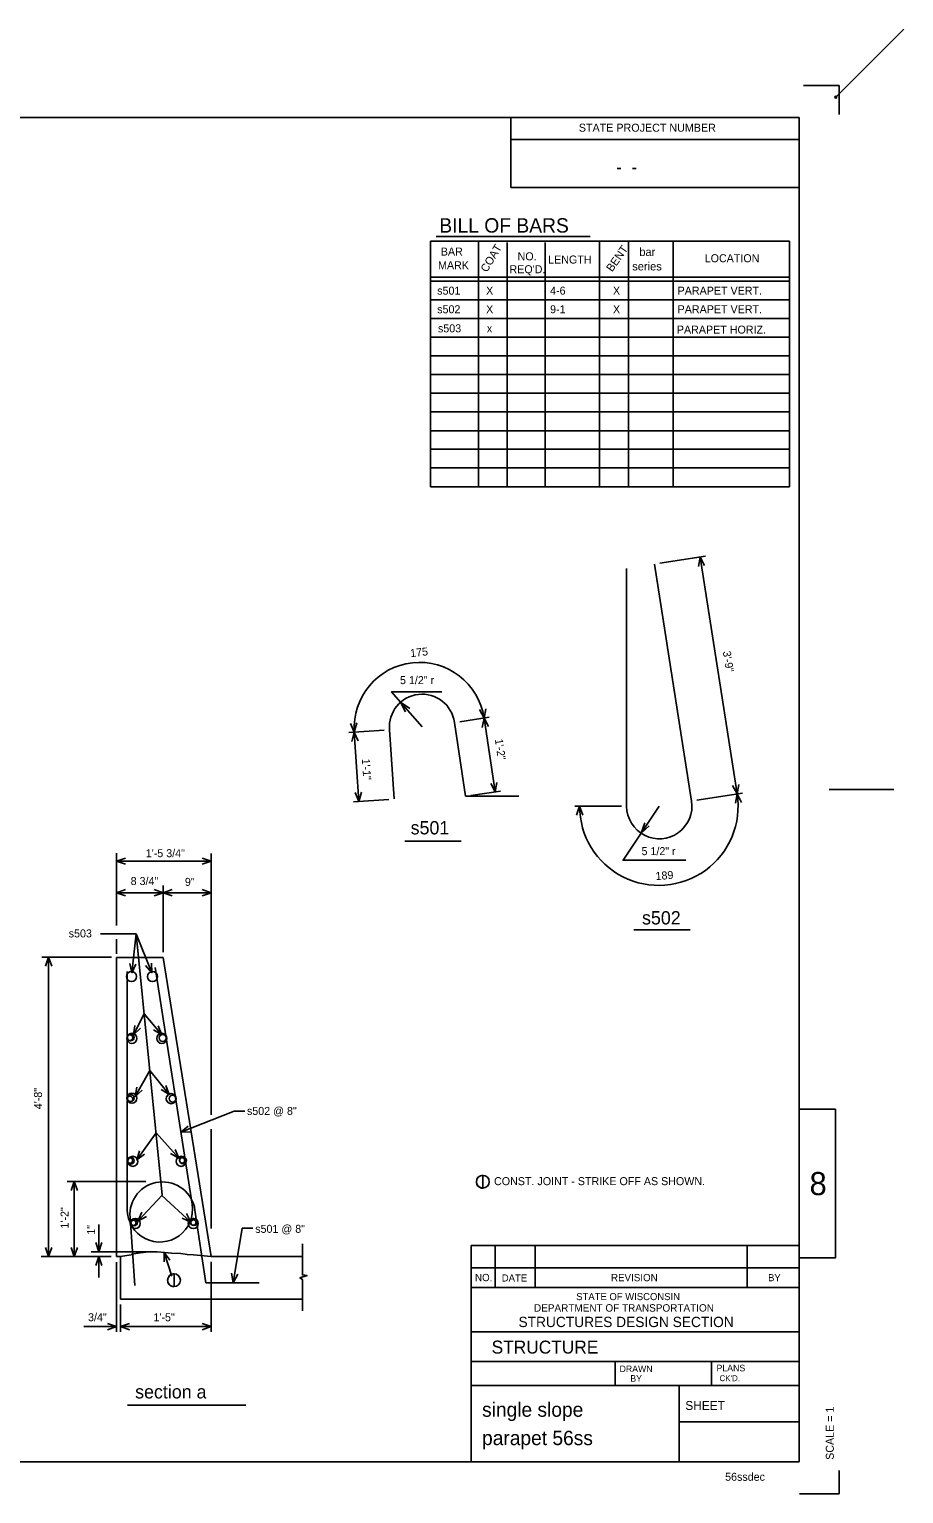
# Model space of a CAD drawing. Extents: x -38.4 to -2.2, y 84.9 to 109.4.
# Drawn here: x -15.84 to -2.17, y 85.97 to 108.85 of the extents above; entities that cross this region are included whole.
import ezdxf

# ---------------------------------------------------------------- set-up
doc = ezdxf.new("R2010")
doc.units = 0
for name, color, linetype in [('Default', 7, 'Continuous'), ('Level 1', 7, 'Continuous'), ('Level 2', 7, 'Continuous'), ('Level 37', 7, 'Continuous'), ('Level 49', 7, 'Continuous')]:
    doc.layers.add(name, color=color, linetype=linetype)

msp = doc.modelspace()

# ---------------------------------------------------------------- linework, layer by layer
at = {"layer": 'Default'}
for p, q in [((-14.473, 94.846), (-14.473, 95.978)), ((-14.473, 95.851), (-12.994, 95.851)), ((-12.994, 94.526), (-12.994, 95.97)), ((-13.744, 94.428), (-13.744, 95.471)), ((-14.473, 95.358), (-13.744, 95.358)), ((-13.744, 95.358), (-12.994, 95.358)), ((-14.168, 94.719), (-14.722, 94.719)), ((-14.232, 94.11), (-14.168, 94.719)), ((-14.168, 94.719), (-13.759, 90.637)), ((-14.168, 94.719), (-13.919, 94.11)), ((-12.994, 91.891), (-12.994, 94.809)), ((-14.473, 94.428), (-14.473, 94.634)), ((-14.473, 94.407), (-14.473, 94.617)), ((-14.55, 94.355), (-15.639, 94.355)), ((-15.533, 89.678), (-15.533, 94.355)), ((-14.473, 94.345), (-13.744, 94.345)), ((-14.473, 94.345), (-14.473, 89.678)), ((-12.994, 89.678), (-13.744, 94.345)), ((-14.304, 94.126), (-14.304, 90.412)), ((-13.291, 90.492), (-13.869, 94.193)), ((-14.206, 93.138), (-14.043, 93.469)), ((-14.043, 93.469), (-13.767, 93.138)), ((-14.181, 92.175), (-13.954, 92.581)), ((-13.954, 92.581), (-13.649, 92.209)), ((-12.633, 91.949), (-13.467, 91.617)), ((-12.466, 91.949), (-12.633, 91.949)), ((-14.156, 91.186), (-13.856, 91.609)), ((-13.856, 91.609), (-13.497, 91.212)), ((-12.994, 90.113), (-12.994, 91.664)), ((-14.017, 90.847), (-15.245, 90.847)), ((-15.133, 89.678), (-15.133, 90.847)), ((-8.748, 90.743), (-8.748, 90.943)), ((-8.748, 90.743), (-8.748, 90.943)), ((-13.759, 90.637), (-14.139, 90.231)), ((-13.311, 90.214), (-13.763, 90.632)), ((-13.078, 89.267), (-13.248, 90.4)), ((-14.75, 89.752), (-14.75, 90.178)), ((-14.189, 89.226), (-14.262, 90.286)), ((-12.509, 90.121), (-12.652, 89.267)), ((-12.342, 90.121), (-12.509, 90.121)), ((-14.557, 89.678), (-15.649, 89.678)), ((-15.213, 89.678), (-15.05, 89.678)), ((-13.943, 89.752), (-14.871, 89.752)), ((-14.75, 89.349), (-14.75, 89.678)), ((-14.473, 89.678), (-14.411, 89.678)), ((-14.411, 89.678), (-14.411, 89.011)), ((-13.611, 89.371), (-13.727, 89.741)), ((-11.568, 89.678), (-12.994, 89.678)), ((-14.473, 89.586), (-14.473, 88.498)), ((-12.994, 89.595), (-12.994, 88.498)), ((-13.573, 89.204), (-13.573, 89.405)), ((-13.078, 89.267), (-12.244, 89.267)), ((-14.411, 89.011), (-11.568, 89.011)), ((-14.411, 88.928), (-14.411, 88.498)), ((-14.473, 88.581), (-14.982, 88.581)), ((-14.411, 88.581), (-12.994, 88.581)), ((-14.302, 87.356), (-12.451, 87.356))]:
    msp.add_line(p, q, dxfattribs=at)
for points in [[(-14.333, 95.803), (-14.473, 95.851), (-14.333, 95.9)], [(-13.135, 95.9), (-12.994, 95.851), (-13.135, 95.803)], [(-14.333, 95.309), (-14.473, 95.358), (-14.333, 95.407)], [(-13.885, 95.407), (-13.744, 95.358), (-13.885, 95.309)], [(-13.603, 95.309), (-13.744, 95.358), (-13.603, 95.407)], [(-13.135, 95.407), (-12.994, 95.358), (-13.135, 95.309)], [(-15.582, 94.214), (-15.533, 94.355), (-15.484, 94.214)], [(-14.169, 94.245), (-14.232, 94.11), (-14.265, 94.256)], [(-13.927, 94.259), (-13.919, 94.11), (-14.018, 94.222)], [(-14.1, 93.243), (-14.206, 93.138), (-14.187, 93.286)], [(-13.82, 93.278), (-13.767, 93.138), (-13.895, 93.216)], [(-14.07, 92.274), (-14.181, 92.175), (-14.155, 92.322)], [(-13.7, 92.349), (-13.649, 92.209), (-13.776, 92.287)], [(-13.318, 91.624), (-13.467, 91.617), (-13.354, 91.714)], [(-14.035, 91.273), (-14.156, 91.186), (-14.114, 91.329)], [(-13.555, 91.349), (-13.497, 91.212), (-13.627, 91.284)], [(-15.182, 90.706), (-15.133, 90.847), (-15.084, 90.706)], [(-14.007, 90.301), (-14.139, 90.231), (-14.078, 90.367)], [(-13.381, 90.346), (-13.311, 90.214), (-13.447, 90.274)], [(-13.355, 90.297), (-13.311, 90.214), (-13.396, 90.252)], [(-15.484, 89.819), (-15.533, 89.678), (-15.582, 89.819)], [(-15.084, 89.819), (-15.133, 89.678), (-15.182, 89.819)], [(-14.701, 89.893), (-14.75, 89.752), (-14.798, 89.893)], [(-14.798, 89.537), (-14.75, 89.678), (-14.701, 89.537)], [(-14.411, 89.678), (-14.245, 89.7), (-14.233, 89.712), (-14.101, 89.734), (-13.966, 89.752), (-13.837, 89.749), (-13.717, 89.737), (-13.616, 89.728), (-13.469, 89.725), (-13.371, 89.71), (-13.269, 89.7), (-12.994, 89.678)], [(-13.731, 89.592), (-13.727, 89.741), (-13.638, 89.621)], [(-11.568, 88.826), (-11.568, 89.319), (-11.609, 89.341), (-11.497, 89.382), (-11.568, 89.388), (-11.568, 89.874)], [(-12.58, 89.398), (-12.652, 89.267), (-12.676, 89.414)], [(-14.614, 88.63), (-14.473, 88.581), (-14.614, 88.533)], [(-14.27, 88.533), (-14.411, 88.581), (-14.27, 88.63)], [(-13.135, 88.63), (-12.994, 88.581), (-13.135, 88.533)]]:
    msp.add_lwpolyline(points, dxfattribs=at)
for points in [[(-8.748, 90.744), (-8.748, 90.943), (-8.748, 90.944), (-8.767, 90.943), (-8.789, 90.937), (-8.807, 90.927), (-8.826, 90.91), (-8.837, 90.895), (-8.846, 90.874), (-8.851, 90.849), (-8.849, 90.825), (-8.844, 90.807), (-8.831, 90.783), (-8.818, 90.77), (-8.802, 90.757), (-8.785, 90.75), (-8.77, 90.746), (-8.762, 90.744)], [(-8.748, 90.744), (-8.748, 90.943), (-8.748, 90.944), (-8.767, 90.943), (-8.789, 90.937), (-8.807, 90.927), (-8.826, 90.91), (-8.837, 90.895), (-8.846, 90.874), (-8.851, 90.849), (-8.849, 90.825), (-8.844, 90.807), (-8.831, 90.783), (-8.818, 90.77), (-8.802, 90.757), (-8.785, 90.75), (-8.77, 90.746), (-8.762, 90.744)], [(-13.573, 89.205), (-13.573, 89.405), (-13.573, 89.405), (-13.592, 89.404), (-13.614, 89.399), (-13.632, 89.388), (-13.651, 89.372), (-13.662, 89.356), (-13.671, 89.335), (-13.676, 89.31), (-13.673, 89.286), (-13.669, 89.269), (-13.656, 89.245), (-13.643, 89.232), (-13.627, 89.219), (-13.61, 89.212), (-13.595, 89.207), (-13.586, 89.206)]]:
    msp.add_lwpolyline(points, close=True, dxfattribs=at)
for centre, radius in [((-14.239, 94.049), 0.0788), ((-13.91, 94.049), 0.0788), ((-14.232, 93.084), 0.0788), ((-14.253, 93.099), 0.0539), ((-14.262, 93.095), 0.0417), ((-13.764, 93.084), 0.0788), ((-13.752, 93.091), 0.0539), ((-14.232, 92.15), 0.0788), ((-14.253, 92.151), 0.0539), ((-13.618, 92.142), 0.0788), ((-13.598, 92.143), 0.0539), ((-14.262, 92.137), 0.0417), ((-14.253, 91.172), 0.0539), ((-14.262, 91.175), 0.0417), ((-14.217, 91.163), 0.0788), ((-13.464, 91.163), 0.0788), ((-13.436, 91.18), 0.0539), ((-13.447, 91.178), 0.0417), ((-8.75, 90.844), 0.1), ((-8.75, 90.844), 0.1), ((-14.18, 90.192), 0.0788), ((-14.199, 90.209), 0.0539), ((-14.208, 90.203), 0.0417), ((-13.274, 90.192), 0.0788), ((-13.266, 90.217), 0.0539), ((-13.272, 90.206), 0.0417), ((-13.575, 89.306), 0.1)]:
    msp.add_circle(centre, radius, dxfattribs=at)
for centre, start, end in [((-13.753, 90.332), 7.615, 185.2003), ((-13.795, 90.412), 180, 9)]:
    msp.add_arc(centre, 0.51, start, end, dxfattribs=at)
at = {"layer": 'Level 1'}
for p, q in [((-3.184, 107.971), (-3.739, 107.971)), ((-3.184, 107.516), (-3.184, 107.971)), ((-3.809, 107.471), (-35.185, 107.471)), ((-8.315, 107.471), (-8.315, 106.375)), ((-3.809, 86.471), (-3.809, 107.471)), ((-8.315, 107.126), (-3.809, 107.126)), ((-8.315, 106.375), (-3.809, 106.375)), ((-5.489, 96.791), (-6.068, 100.492)), ((-5.985, 100.505), (-5.274, 100.616)), ((-5.356, 100.603), (-4.778, 96.902)), ((-6.503, 100.425), (-6.503, 96.711)), ((-9.699, 97.951), (-10.034, 98.336)), ((-9.02, 96.865), (-9.193, 98.019)), ((-9.111, 98.031), (-8.649, 98.1)), ((-8.731, 98.088), (-8.558, 96.934)), ((-10.29, 97.899), (-10.842, 97.861)), ((-10.685, 96.786), (-10.758, 97.867)), ((-10.133, 96.824), (-10.207, 97.905)), ((-10.217, 96.818), (-10.768, 96.781)), ((-9.02, 96.865), (-8.187, 96.865)), ((-8.938, 96.877), (-8.476, 96.946)), ((-5.407, 96.804), (-4.695, 96.915)), ((-6.586, 96.711), (-7.313, 96.711)), ((-5.993, 96.711), (-6.277, 96.287)), ((-9.97, 96.166), (-9.091, 96.166)), ((-6.392, 94.779), (-5.513, 94.779)), ((-8.934, 89.846), (-3.806, 89.846)), ((-8.934, 89.19), (-8.934, 89.846)), ((-8.555, 89.19), (-8.555, 89.846)), ((-7.93, 89.19), (-7.93, 89.846)), ((-4.618, 89.19), (-4.618, 89.846)), ((-8.934, 89.502), (-3.806, 89.502)), ((-8.934, 86.471), (-8.934, 89.19)), ((-8.934, 89.19), (-3.806, 89.19)), ((-8.934, 88.502), (-3.806, 88.502)), ((-8.934, 88.034), (-3.806, 88.034)), ((-6.683, 87.659), (-6.683, 88.034)), ((-5.176, 87.659), (-5.176, 88.034)), ((-8.934, 87.659), (-3.806, 87.659)), ((-5.684, 86.471), (-5.684, 87.659)), ((-5.683, 87.096), (-3.809, 87.096)), ((-35.185, 86.471), (-3.809, 86.471)), ((-3.184, 85.971), (-3.184, 86.334)), ((-3.802, 85.971), (-3.184, 85.971))]:
    msp.add_line(p, q, dxfattribs=at)
for points in [[(-5.382, 100.456), (-5.356, 100.603), (-5.286, 100.471)], [(-10.034, 98.336), (-10.175, 98.499), (-9.388, 98.499)], [(-9.956, 98.183), (-10.034, 98.336), (-9.893, 98.238)], [(-8.704, 98.234), (-8.731, 98.088), (-8.8, 98.22)], [(-10.719, 98.011), (-10.758, 97.867), (-10.817, 98.004)], [(-8.758, 97.941), (-8.731, 98.088), (-8.662, 97.956)], [(-10.797, 97.723), (-10.758, 97.867), (-10.7, 97.73)], [(-8.531, 97.081), (-8.558, 96.934), (-8.627, 97.066)], [(-4.751, 97.049), (-4.778, 96.902), (-4.847, 97.034)], [(-10.646, 96.93), (-10.685, 96.786), (-10.743, 96.924)], [(-4.804, 96.756), (-4.778, 96.902), (-4.708, 96.771)], [(-7.286, 96.57), (-7.238, 96.711), (-7.189, 96.57)], [(-6.15, 96.402), (-6.277, 96.287), (-6.219, 96.449)], [(-6.277, 96.287), (-6.558, 95.866), (-5.579, 95.866)]]:
    msp.add_lwpolyline(points, dxfattribs=at)
msp.add_lwpolyline([(-3.809, 91.976), (-3.242, 91.976), (-3.242, 89.654), (-3.809, 89.654)], close=True, dxfattribs=at)
for centre, radius, start, end in [((-9.74, 97.937), 1.02, 8.5231, 183.9058), ((-9.699, 97.951), 0.51, 7.615, 185.2003), ((-6, 96.711), 1.238, 180, 8.8807), ((-5.993, 96.711), 0.51, 180, 9)]:
    msp.add_arc(centre, radius, start, end, dxfattribs=at)
at = {"layer": 'Level 2'}
for p, q in [((-3.235, 107.786), (-2.175, 108.847)), ((-9.568, 105.536), (-8.343, 105.536)), ((-9.568, 105.536), (-9.568, 101.702)), ((-9.48, 105.608), (-7.072, 105.608)), ((-8.818, 105.536), (-8.818, 101.702)), ((-8.368, 105.519), (-8.368, 101.702)), ((-8.343, 105.536), (-7.775, 105.536)), ((-7.775, 105.536), (-5.775, 105.536)), ((-7.775, 105.519), (-7.775, 101.702)), ((-6.925, 105.536), (-6.925, 101.702)), ((-6.475, 105.536), (-6.475, 101.702)), ((-5.775, 105.536), (-3.958, 105.536)), ((-5.775, 105.536), (-5.775, 101.702)), ((-3.958, 105.536), (-3.958, 101.702)), ((-9.568, 104.973), (-7.775, 104.973)), ((-9.568, 104.911), (-7.775, 104.911)), ((-7.775, 104.973), (-5.775, 104.973)), ((-7.775, 104.911), (-5.775, 104.911)), ((-5.775, 104.973), (-3.958, 104.973)), ((-5.775, 104.911), (-3.958, 104.911)), ((-9.568, 104.619), (-7.775, 104.619)), ((-7.775, 104.619), (-5.775, 104.619)), ((-5.775, 104.619), (-3.958, 104.619)), ((-9.568, 104.327), (-7.775, 104.327)), ((-7.775, 104.327), (-5.775, 104.327)), ((-5.775, 104.327), (-3.958, 104.327)), ((-9.568, 104.036), (-7.775, 104.036)), ((-7.775, 104.036), (-5.775, 104.036)), ((-5.775, 104.036), (-3.958, 104.036)), ((-9.568, 103.744), (-7.775, 103.744)), ((-7.775, 103.744), (-5.775, 103.744)), ((-5.775, 103.744), (-3.958, 103.744)), ((-9.568, 103.452), (-7.775, 103.452)), ((-7.775, 103.452), (-5.775, 103.452)), ((-5.775, 103.452), (-3.958, 103.452)), ((-9.568, 103.161), (-7.775, 103.161)), ((-7.775, 103.161), (-5.775, 103.161)), ((-5.775, 103.161), (-3.958, 103.161)), ((-9.568, 102.869), (-7.775, 102.869)), ((-7.775, 102.869), (-5.775, 102.869)), ((-5.775, 102.869), (-3.958, 102.869)), ((-9.568, 102.577), (-7.775, 102.577)), ((-7.775, 102.577), (-5.775, 102.577)), ((-5.775, 102.577), (-3.958, 102.577)), ((-9.568, 102.286), (-7.775, 102.286)), ((-7.775, 102.286), (-5.775, 102.286)), ((-5.775, 102.286), (-3.958, 102.286)), ((-9.568, 101.994), (-7.775, 101.994)), ((-7.775, 101.994), (-5.775, 101.994)), ((-5.775, 101.994), (-3.958, 101.994)), ((-9.568, 101.702), (-7.775, 101.702)), ((-9.568, 101.702), (-7.775, 101.702)), ((-7.775, 101.702), (-3.958, 101.702)), ((-7.775, 101.702), (-3.958, 101.702))]:
    msp.add_line(p, q, dxfattribs=at)
at = {"layer": 'Level 37'}
msp.add_line((-3.339, 96.971), (-2.329, 96.971), dxfattribs=at)
at = {"layer": 'Level 49'}
msp.add_circle((-3.236, 107.786), 0.0152, dxfattribs=at)

# ---------------------------------------------------------------- texts
at = {"layer": 'Default'}
for s, height, p in [('1\'-5 3/4"', 0.125, (-14.016, 95.914)), ('8 3/4"', 0.125, (-14.252, 95.479)), ('9"', 0.125, (-13.405, 95.466)), ('s503', 0.125, (-15.22, 94.661)), ('s502 @ 8"', 0.125, (-12.435, 91.888)), ('CONST. JOINT - STRIKE OFF AS SHOWN.', 0.125, (-8.575, 90.791)), ('CONST. JOINT - STRIKE OFF AS SHOWN.', 0.125, (-8.575, 90.791)), ('s501 @ 8"', 0.125, (-12.306, 90.046)), ('3/4"', 0.125, (-14.918, 88.665)), ('1\'-5"', 0.125, (-13.896, 88.665)), ('section a', 0.2083, (-14.182, 87.459)), ('56ssdec', 0.125, (-4.965, 86.173))]:
    msp.add_text(s, height=height, dxfattribs=at).set_placement(p)
for s, p in [('4\'-8"', (-15.637, 91.977)), ('1\'-2"', (-15.222, 90.113)), ('1"', (-14.807, 90.016))]:
    msp.add_text(s, height=0.125, rotation=90, dxfattribs=at).set_placement(p)
at = {"layer": 'Level 1'}
for s, height, p in [('STATE PROJECT NUMBER', 0.12525, (-7.25, 107.247)), ('    -  -  ', 0.2023, (-6.969, 106.594)), ('5 1/2" r', 0.125, (-10.044, 98.618)), ('s501', 0.2083, (-9.878, 96.27)), ('5 1/2" r', 0.125, (-6.271, 95.946)), ('s502', 0.2083, (-6.263, 94.863)), ('8', 0.361, (-3.646, 90.635)), ('NO.', 0.1139, (-8.872, 89.291)), ('DATE', 0.1109, (-8.454, 89.286)), ('REVISION', 0.1142, (-6.748, 89.29)), ('BY', 0.1108, (-4.294, 89.29)), ('STATE OF WISCONSIN', 0.11076, (-7.291, 88.995)), ('DEPARTMENT OF TRANSPORTATION', 0.11643, (-7.951, 88.815)), ('STRUCTURES DESIGN SECTION', 0.1605, (-8.193, 88.574)), ('STRUCTURE', 0.2022, (-8.613, 88.16)), ('DRAWN', 0.1022, (-6.614, 87.871)), ('PLANS', 0.1023, (-5.099, 87.883)), ('BY', 0.102, (-6.446, 87.721)), ("CK'D.", 0.0927, (-5.052, 87.729)), (' single slope ', 0.22392, (-8.845, 87.173)), ('SHEET', 0.1387, (-5.587, 87.28)), (' parapet 56ss ', 0.22392, (-8.845, 86.73))]:
    msp.add_text(s, height=height, dxfattribs=at).set_placement(p)
for s, rotation, p in [('175', 6.2145, (-9.879, 99.038)), ('3\'-9"', 278.8807, (-5.002, 99.126)), ('1\'-2"', 278.5231, (-8.563, 97.754)), ('1\'-1"', 273.9058, (-10.64, 97.449)), ('189', 4.4403, (-6.047, 95.556)), ('SCALE = 1        ', 90, (-3.267, 86.5))]:
    msp.add_text(s, height=0.125, rotation=rotation, dxfattribs=at).set_placement(p)
at = {"layer": 'Level 2'}
for s, height, p in [('BILL OF BARS', 0.225, (-9.43, 105.671)), ('BAR', 0.125, (-9.407, 105.312)), ('NO.', 0.125, (-8.207, 105.238)), ('LENGTH', 0.125, (-7.73, 105.188)), ('bar', 0.1294, (-6.305, 105.305)), ('LOCATION', 0.125, (-5.284, 105.208)), ('MARK', 0.125, (-9.45, 105.098)), ("REQ'D.", 0.125, (-8.334, 105.036)), ('series', 0.1294, (-6.416, 105.08)), ('s501', 0.125, (-9.463, 104.702)), ('X', 0.125, (-8.699, 104.702)), (' 4-6 ', 0.125, (-7.746, 104.702)), ('X', 0.125, (-6.717, 104.702)), ('PARAPET VERT.   ', 0.125, (-5.707, 104.702)), ('s502', 0.125, (-9.463, 104.411)), ('X', 0.125, (-8.699, 104.411)), (' 9-1 ', 0.125, (-7.746, 104.411)), ('X', 0.125, (-6.717, 104.411)), ('PARAPET VERT.   ', 0.125, (-5.707, 104.411)), ('s503', 0.125, (-9.451, 104.113)), ('x', 0.125, (-8.687, 104.113)), ('PARAPET HORIZ.  ', 0.125, (-5.719, 104.093))]:
    msp.add_text(s, height=height, dxfattribs=at).set_placement(p)
for s, rotation, p in [('COAT', 59.0083, (-8.687, 105.041)), ('BENT', 54.9994, (-6.73, 105.049))]:
    msp.add_text(s, height=0.125, rotation=rotation, dxfattribs=at).set_placement(p)

doc.saveas('drawing.dxf')
